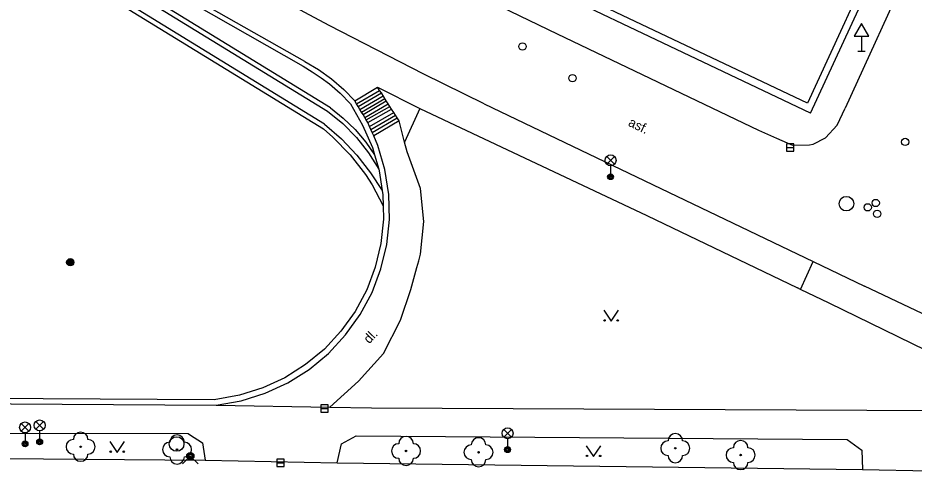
# Model space of a CAD drawing. Extents: x -600309 to -598967, y -1161267 to -1160292.
# Drawn here: x -600033.9 to -599972.5, y -1160620.1 to -1160588.9 of the extents above; entities that cross this region are included whole.
import ezdxf

# ---------------------------------------------------------------- set-up
doc = ezdxf.new("R2010")
doc.units = 0
for name, color, linetype in [('Level 10', 7, 'Continuous'), ('Level 11', 7, 'Continuous'), ('Level 22', 7, 'Continuous'), ('Level 25', 7, 'Continuous'), ('Level 27', 7, 'Continuous'), ('Level 28', 7, 'Continuous'), ('Level 31', 7, 'Continuous'), ('Level 33', 7, 'Continuous'), ('Level 34', 7, 'Continuous'), ('Level 36', 7, 'Continuous'), ('Level 40', 7, 'Continuous'), ('Level 7', 7, 'Continuous')]:
    doc.layers.add(name, color=color, linetype=linetype)

msp = doc.modelspace()

# ---------------------------------------------------------------- linework, layer by layer
at = {"layer": 'Level 10'}
for points in [[(-599935.03, -1160508.16), (-599937.49, -1160511.84), (-599937.56, -1160511.95), (-599938.03, -1160512.7), (-599939.64, -1160515.26), (-599941.75, -1160518.63), (-599946.15, -1160526.95), (-599959.57, -1160556.4699), (-599964.29, -1160566.81), (-599966.33, -1160571.27), (-599969.39, -1160577.98), (-599972.6, -1160585.01), (-599977.2, -1160595.1)], [(-600029.27, -1160572.7), (-600024.61, -1160575.4), (-600019.51, -1160578.26), (-600013, -1160581.84), (-600007.82, -1160584.6), (-600002.76, -1160587.15), (-599996.93, -1160589.99), (-599983.13, -1160596.6), (-599981.9, -1160597.15)], [(-600001.94, -1160594.8), (-600006.09, -1160592.75), (-600012.57, -1160589.4099), (-600017.92, -1160586.53), (-600022.78, -1160583.85), (-600028.27, -1160580.8), (-600029.82, -1160579.77)], [(-600001.94, -1160594.8), (-599979.38, -1160605.62), (-599975.88, -1160607.3)], [(-599977.75, -1160596.26), (-599977.2, -1160595.1)], [(-599981.9, -1160597.15), (-599980.81, -1160597.63), (-599979.63, -1160597.62), (-599979.39, -1160597.56), (-599978.55, -1160597.14), (-599977.75, -1160596.26)], [(-599964.87, -1160612.53), (-599975.88, -1160607.3)], [(-600037.7199, -1160619.11), (-600021.07, -1160619.25)], [(-600021.07, -1160619.25), (-600012.03, -1160619.43)], [(-600012.03, -1160619.43), (-599976, -1160619.89)], [(-599976, -1160619.89), (-599966.83, -1160620.07)]]:
    msp.add_lwpolyline(points, dxfattribs=at)
at = {"layer": 'Level 11'}
for points in [[(-600012.49, -1160595.07), (-600057.96, -1160567.15)], [(-600058.13, -1160567.42), (-600012.68, -1160595.3)], [(-600041.12, -1160580.01), (-600038.68, -1160581.51), (-600038.26, -1160580.98), (-600012.96, -1160596.52)], [(-600012.88, -1160596.18), (-600038.34, -1160580.55), (-600038.76, -1160581.12), (-600040.96, -1160579.76)], [(-600010.81, -1160594.6), (-600009.25, -1160593.65)], [(-600010.69, -1160594.8), (-600009.11, -1160593.87)], [(-600010.58, -1160594.98), (-600008.99, -1160594.05)], [(-600009.25, -1160593.65), (-600006.35, -1160595.12)], [(-600007.78, -1160595.9699), (-600007.91, -1160595.76), (-600008.03, -1160595.57), (-600008.14, -1160595.4), (-600008.29, -1160595.16), (-600008.42, -1160594.97), (-600008.53, -1160594.79), (-600008.66, -1160594.59), (-600008.99, -1160594.05), (-600009.11, -1160593.87), (-600009.25, -1160593.65)], [(-600010.46, -1160595.18), (-600008.87, -1160594.25)], [(-600010.35, -1160595.36), (-600008.76, -1160594.43)], [(-600010.25, -1160595.53), (-600008.66, -1160594.59)], [(-600010.13, -1160595.73), (-600008.53, -1160594.79)], [(-600012.68, -1160595.3), (-600011.64, -1160596.14), (-600010.7, -1160597.1), (-600009.87, -1160598.15), (-600009.17, -1160599.29)], [(-600012.49, -1160595.07), (-600011.6, -1160595.77), (-600010.78, -1160596.56), (-600010.05, -1160597.43), (-600009.46, -1160598.29)], [(-600010.04, -1160595.89), (-600008.42, -1160594.97)], [(-600009.92, -1160596.08), (-600008.29, -1160595.16)], [(-600009.8, -1160596.36), (-600008.14, -1160595.4)], [(-600006.35, -1160595.12), (-600007.4, -1160597.42)], [(-600006.35, -1160595.12), (-599990.8, -1160602.46), (-599980.46, -1160607.43)], [(-600012.52, -1160615.62), (-600010.556, -1160613.818), (-600008.854, -1160611.931), (-600007.67, -1160609.637), (-600006.967, -1160607.528), (-600006.554, -1160606.0374), (-600006.427, -1160605.5788), (-600006.301, -1160605.124), (-600006.079, -1160602.867), (-600006.301, -1160600.61), (-600007.226, -1160598.094), (-600007.4, -1160597.42), (-600007.78, -1160595.97)], [(-600009.71, -1160596.55), (-600008.03, -1160595.57)], [(-600009.62, -1160596.77), (-600007.91, -1160595.76)], [(-600007.78, -1160595.9699), (-600009.52, -1160597)], [(-600012.96, -1160596.52), (-600012.32, -1160597.08), (-600011.13, -1160598.3), (-600010.09, -1160599.64), (-600009.63, -1160600.36), (-600008.87, -1160601.79)], [(-600012.88, -1160596.18), (-600011.73, -1160597.19), (-600010.67, -1160598.31), (-600009.73, -1160599.52), (-600008.94, -1160600.75)], [(-599980.26, -1160607.53), (-599979.38, -1160605.62)], [(-599978.28, -1160608.48), (-599980.26, -1160607.53), (-599980.46, -1160607.43)], [(-599968.84, -1160613.09), (-599978.28, -1160608.48)], [(-600020.31, -1160615.48), (-600012.52, -1160615.62)], [(-600012.52, -1160615.62), (-600009.6599, -1160615.67), (-599975.72, -1160615.81), (-599967.54, -1160615.84)], [(-600037.7199, -1160619.11), (-600037.42, -1160617.79), (-600036.46, -1160617.4), (-600022.24, -1160617.4099), (-600022.14, -1160617.48), (-600021.26, -1160618.07), (-600021.07, -1160619.25)], [(-600012.03, -1160619.43), (-600011.7199, -1160618.12), (-600010.71, -1160617.59), (-599977.05, -1160617.83), (-599976.06, -1160618.57), (-599976, -1160619.89)]]:
    msp.add_lwpolyline(points, dxfattribs=at)
at = {"layer": 'Level 22'}
for centre in [(-600029.61, -1160618.33), (-600023, -1160618.52), (-600007.3, -1160618.62), (-600002.33, -1160618.71), (-599988.84, -1160618.43), (-599984.36, -1160618.9)]:
    msp.add_circle(centre, 0.05, dxfattribs=at)
for centre, start, end in [((-600029.61, -1160617.83), 0, 180), ((-600023, -1160618.02), 0, 180), ((-599988.84, -1160617.93), 0, 180), ((-600030.11, -1160618.33), 90, 270), ((-600029.11, -1160618.33), 270, 90), ((-600023.5, -1160618.52), 90, 270), ((-600022.5, -1160618.52), 270, 90), ((-600007.8, -1160618.62), 90, 270), ((-600007.3, -1160618.12), 0, 180), ((-600006.8, -1160618.62), 270, 90), ((-600002.33, -1160618.21), 0, 180), ((-599989.34, -1160618.43), 90, 270), ((-599988.34, -1160618.43), 270, 90), ((-599984.36, -1160618.4), 0, 180), ((-600002.83, -1160618.71), 90, 270), ((-600001.83, -1160618.71), 270, 90), ((-599984.86, -1160618.9), 90, 270), ((-599983.86, -1160618.9), 270, 90), ((-600029.61, -1160618.83), 180, 0), ((-600023, -1160619.02), 180, 0), ((-600007.3, -1160619.12), 180, 0), ((-600002.33, -1160619.21), 180, 0), ((-599988.84, -1160618.93), 180, 0), ((-599984.36, -1160619.4), 180, 0)]:
    msp.add_arc(centre, 0.5, start, end, dxfattribs=at)
at = {"layer": 'Level 25'}
for radius in [0.25, 0.2, 0.15, 0.1, 0.05]:
    msp.add_circle((-600030.32, -1160605.67), radius, dxfattribs=at)
at = {"layer": 'Level 27'}
for p, q in [((-599981.21, -1160597.8), (-599980.71, -1160597.8)), ((-600013.15, -1160615.71), (-600012.65, -1160615.71)), ((-600016.1599, -1160619.44), (-600015.6599, -1160619.44))]:
    msp.add_line(p, q, dxfattribs=at)
for points in [[(-599981.21, -1160598.05), (-599980.71, -1160598.05), (-599980.71, -1160597.55), (-599981.21, -1160597.55)], [(-600013.15, -1160615.96), (-600012.65, -1160615.96), (-600012.65, -1160615.46), (-600013.15, -1160615.46)], [(-600016.1599, -1160619.69), (-600015.6599, -1160619.69), (-600015.6599, -1160619.19), (-600016.1599, -1160619.19)]]:
    msp.add_lwpolyline(points, close=True, dxfattribs=at)
for centre in [(-599977.11, -1160601.65), (-600023.03, -1160618.14)]:
    msp.add_circle(centre, 0.5, dxfattribs=at)
at = {"layer": 'Level 28'}
for centre in [(-599999.32, -1160590.86), (-599995.89, -1160593.03), (-599973.08, -1160597.4099), (-599975.1, -1160601.6), (-599975.65, -1160601.9), (-599975, -1160602.35)]:
    msp.add_circle(centre, 0.25, dxfattribs=at)
at = {"layer": 'Level 31'}
msp.add_lwpolyline([(-600022.62, -1160619.4999), (-600022.09, -1160618.9699), (-600021.56, -1160619.4999)], dxfattribs=at)
for radius in [0.25, 0.18, 0.11]:
    msp.add_circle((-600022.09, -1160618.9699), radius, dxfattribs=at)
at = {"layer": 'Level 33'}
for p, q in [((-599993.545, -1160598.94), (-599993.015, -1160598.41)), ((-599993.545, -1160598.41), (-599993.015, -1160598.94)), ((-599993.28, -1160599.05), (-599993.28, -1160599.8)), ((-600033.685, -1160617.27), (-600033.155, -1160616.74)), ((-600033.685, -1160616.74), (-600033.155, -1160617.27)), ((-600032.685, -1160617.13), (-600032.155, -1160616.6)), ((-600032.685, -1160616.6), (-600032.155, -1160617.13)), ((-600033.42, -1160617.38), (-600033.42, -1160618.13)), ((-600032.42, -1160617.24), (-600032.42, -1160617.99)), ((-600000.605, -1160617.67), (-600000.075, -1160617.14)), ((-600000.605, -1160617.14), (-600000.075, -1160617.67)), ((-600000.34, -1160617.78), (-600000.34, -1160618.53))]:
    msp.add_line(p, q, dxfattribs=at)
for centre, radius in [((-599993.28, -1160598.675), 0.375), ((-599993.28, -1160599.8), 0.2), ((-599993.28, -1160599.8), 0.1445), ((-599993.28, -1160599.8), 0.0876), ((-600033.42, -1160617.005), 0.375), ((-600032.42, -1160616.865), 0.375), ((-600000.34, -1160617.405), 0.375), ((-600033.42, -1160618.13), 0.2), ((-600033.42, -1160618.13), 0.1445), ((-600033.42, -1160618.13), 0.0876), ((-600032.42, -1160617.99), 0.2), ((-600032.42, -1160617.99), 0.1445), ((-600032.42, -1160617.99), 0.0876), ((-600000.34, -1160618.53), 0.2), ((-600000.34, -1160618.53), 0.1445), ((-600000.34, -1160618.53), 0.0876)]:
    msp.add_circle(centre, radius, dxfattribs=at)
at = {"layer": 'Level 34'}
for p, q in [((-599976.07, -1160590.152), (-599976.07, -1160591.17)), ((-599976.32, -1160591.17), (-599975.82, -1160591.17))]:
    msp.add_line(p, q, dxfattribs=at)
msp.add_lwpolyline([(-599976.57, -1160590.152), (-599975.57, -1160590.152), (-599976.07, -1160589.286)], close=True, dxfattribs=at)
at = {"layer": 'Level 36'}
for points in [[(-599993.74, -1160608.96), (-599993.24, -1160609.71), (-599992.74, -1160608.96)], [(-600027.6, -1160617.97), (-600027.1, -1160618.72), (-600026.6, -1160617.97)], [(-599994.94, -1160618.26), (-599994.44, -1160619.01), (-599993.94, -1160618.26)]]:
    msp.add_lwpolyline(points, dxfattribs=at)
for centre in [(-599993.6902, -1160609.6598), (-599992.7908, -1160609.6598), (-600027.5502, -1160618.6698), (-600026.6508, -1160618.6698), (-599994.8902, -1160618.9598), (-599993.9908, -1160618.9598)]:
    msp.add_circle(centre, 0.05, dxfattribs=at)
at = {"layer": 'Level 7'}
for points in [[(-600057.51, -1160566.44), (-600040.51, -1160577.1), (-600033.27, -1160581.42), (-600014.36, -1160592.2199)], [(-600014.25, -1160591.88), (-600033.15, -1160581.17), (-600040.38, -1160576.8), (-600057.33, -1160566.15)], [(-599979.56, -1160595.43), (-600006.69, -1160582.5)], [(-599974.45, -1160583.15), (-599979.77, -1160594.76), (-600006.5, -1160582.06)], [(-599979.56, -1160595.43), (-599974, -1160583.36)], [(-600014.36, -1160592.2199), (-600013.73, -1160592.59), (-600013.13, -1160593), (-600012.55, -1160593.43), (-600011.82, -1160594.07), (-600011.12, -1160594.79)], [(-600014.25, -1160591.88), (-600013.3, -1160592.44), (-600012.4099, -1160593.08), (-600011.57, -1160593.81), (-600010.81, -1160594.6)], [(-600011.12, -1160594.79), (-600010.29, -1160596.25), (-600009.61, -1160597.79), (-600009.46, -1160598.29)], [(-600009.52, -1160597), (-600009.62, -1160596.77), (-600009.71, -1160596.55), (-600009.8, -1160596.36), (-600009.92, -1160596.08), (-600010.04, -1160595.89), (-600010.13, -1160595.73), (-600010.25, -1160595.53), (-600010.35, -1160595.36), (-600010.46, -1160595.18), (-600010.58, -1160594.98), (-600010.69, -1160594.8), (-600010.81, -1160594.6)], [(-600020.31, -1160615.48), (-600018.61, -1160615.18), (-600016.9699, -1160614.6599), (-600015.4099, -1160613.94), (-600013.95, -1160613.02), (-600012.62, -1160611.92), (-600011.45, -1160610.6599), (-600010.45, -1160609.25), (-600009.63, -1160607.74), (-600009.02, -1160606.13), (-600008.62, -1160604.45), (-600008.44, -1160602.74), (-600008.49, -1160601.01), (-600008.75, -1160599.31), (-600009.23, -1160597.6599), (-600009.52, -1160597)], [(-600009.46, -1160598.29), (-600009.17, -1160599.29)], [(-600009.17, -1160599.29), (-600009.14, -1160599.4), (-600008.94, -1160600.75)], [(-600008.94, -1160600.75), (-600008.89, -1160601.05), (-600008.87, -1160601.79)], [(-600008.87, -1160601.79), (-600008.85, -1160602.7199), (-600009.02, -1160604.38), (-600009.4099, -1160606.01), (-600010, -1160607.57), (-600010.79, -1160609.04), (-600011.76, -1160610.4), (-600012.9, -1160611.63), (-600014.19, -1160612.69), (-600015.6, -1160613.59), (-600017.12, -1160614.29), (-600018.71, -1160614.79), (-600020.46, -1160615.11)], [(-600087.14, -1160615.04), (-600020.31, -1160615.48)], [(-600020.46, -1160615.11), (-600086.94, -1160614.7199)]]:
    msp.add_lwpolyline(points, dxfattribs=at)

# ---------------------------------------------------------------- texts
at = {"layer": 'Level 40'}
for s, height, rotation, p in [('asf.', 0.65, 334.406256, (-599992.12, -1160596.28)), ('dl.', 0.64999, 46.565069, (-600009.82, -1160611.3))]:
    msp.add_text(s, height=height, rotation=rotation, dxfattribs=at).set_placement(p)

doc.saveas('drawing.dxf')
